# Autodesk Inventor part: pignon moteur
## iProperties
Author: Administrateur
Shininess: 20.0
PropertySet Name: _Private Model Information
Length Units: 11269
Angle Units: 11283
Time Units: 11279
Mass Units: 11290
Length Display Precision: 3
Angle Display Precision: 2
Compacted: False
Created: 2001-04
Part Number: pignon moteur
Material: Par défaut
Document SubType Name: Modélisation
Designer: Administrateur
Control State: 0
Master: False
Checked Out: False
PropertySet Name: Design Tracking Control
Density: 0.0
Volumn: 0.0
Area: 0.0
PropertySet Name: Model Information
